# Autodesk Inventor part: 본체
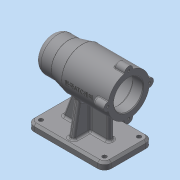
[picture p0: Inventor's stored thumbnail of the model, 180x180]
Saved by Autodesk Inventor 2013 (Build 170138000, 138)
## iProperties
Created: 2019-07
Part Number: 본체
Material: 일반
Document SubType Name: Modeling
Designer: dgall
Density: 1 g/cm^3
Author: dgall
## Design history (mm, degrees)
sketch "스케치1"
  geometry: L1 (0, 0)-(112, 0); L2 (112, 0)-(112, 70); L3 (112, 70)-(0, 70); L4 (0, 70)-(0, 0)
  constraints: 8 end point, 2 parallel, 1 horizontal, 1 perpendicular
  dimensions: "d5" = 70 distance of L1.end L2.end; "d6" = 112 distance of L2.end L3.end
extrude "돌출1" new body sketch "스케치1" distance "d7" = 10; taper "d8" = 0 deg
fillet "모깎기1" dims "d9" = 10
chamfer "모따기1" distance "d10" = 3; stored, may be unused: second distance "d11" = 2, angle "d12" = 45 deg
hole "구멍1" diameter "d15" = 6; stored, may be unused: countersink angle "d19" = 90 deg, drill point angle "d21" = 118 deg; dims "d13" = 10, "d14" = 10, "d16" = 6, "d17" = 4, "d18" = 2, "d20" = 27.5
hole "구멍2" diameter "d24" = 6; stored, may be unused: countersink angle "d28" = 90 deg, drill point angle "d30" = 118 deg; dims "d22" = 10, "d23" = 10, "d25" = 6, "d26" = 4, "d27" = 2, "d29" = 27.5
hole "구멍3" diameter "d33" = 6; stored, may be unused: countersink angle "d37" = 90 deg, drill point angle "d39" = 118 deg; dims "d31" = 10, "d32" = 10, "d34" = 6, "d35" = 4, "d36" = 2, "d38" = 27.5
hole "구멍4" diameter "d42" = 6; stored, may be unused: countersink angle "d46" = 90 deg, drill point angle "d48" = 118 deg; dims "d40" = 10, "d41" = 10, "d43" = 6, "d44" = 4, "d45" = 2, "d47" = 27.5
node "작업 평면2"
sketch "스케치2"
  geometry: L1 (0, 0)-(-112, 0); L2 (-56, 0)-(-56, 80); L3 (-56, 80)-(-112, 80); L4 (-56, 80)-(0, 80); L5 (-112, 80)-(-112, 101); L6 (-112, 101)-(-97, 101); L7 (-97, 101)-(-97, 101); L8 (-94, 104)-(-46, 104); L9 (-43, 101)-(-43, 101); L10 (-43, 101)-(-31.3, 101); L11 (-31, 100.7)-(-31, 97.5); L12 (-31, 97.5)-(-13.3, 97.5); L13 (-13, 97.2)-(-13, 96); L14 (-13, 96)-(-9.3, 96); L15 (-9, 95.7)-(-9, 90.5); L16 (-9, 90.5)-(-9, 90.5); L17 (-6, 87.5)-(-6, 80); L18 (0, 80)-(0, 95); L19 (-10, 105)-(-25, 105); L20 (-25, 105)-(-45, 110); L21 (-45, 110)-(-112, 110); L22 (-112, 110)-(-112, 101); A1 r 0.3 centre (-9.3, 95.7) between (-9, 95.7) and (-9.3, 96); A2 r 0.3 centre (-13.3, 97.2) between (-13, 97.2) and (-13.3, 97.5); A3 r 0.3 centre (-31.3, 100.7) between (-31, 100.7) and (-31.3, 101); A4 r 3 centre (-46, 101) between (-43, 101) and (-46, 104); A5 r 3 centre (-94, 101) between (-94, 104) and (-97, 101); A6 r 3 centre (-9, 87.5) between (-6, 87.5) and (-9, 90.5); A7 r 10 centre (-10, 95) between (0, 95) and (-10, 105); 7 further points
  constraints: 44 end point, 17 perpendicular, 15 point on line, 14 point on circle, 14 tangent, 7 centre point, 3 equal radius, 2 parallel, 1 collinear, 1 horizontal, 1 midpoint
  dimensions: "d50" = 112 distance of L1.start L1.end; "d54" = 80 distance of L2.start L2.end; "d55" = 21 distance of L3.end L5.end; "d57" = 48 diameter of point (-97, 104) L3; "d58" = 54 distance of point (-97, 104) point (-43, 104); "d59" = 56 distance from line of L2.end L5; "d60" = 42 diameter of L9.end L4; "d61" = 12 distance of L9.end point (-31, 101); "d62" = 35 diameter of L11.end L4; "d63" = 18 distance of L11.end point (-13, 97.5); "d64" = 32 diameter of L13.end L4; "d65" = 4 distance of L13.end point (-9, 96); "d66" = 21 diameter of L15.end L4; "d67" = 3 distance of L15.end point (-6, 90.5); "d68" = 0.3 radius of A1; "d69" = 3 radius of A4; "d70" = 50 diameter of point (0, 105) L4; "d71" = 25 distance of point (0, 105) L19.end; "d72" = 60 diameter of L20.end L4; "d73" = 45 horizontal distance of point (0, 105) L20.end; "d74" = 15 distance of L5.end L6.end; "d75" = 112 horizontal distance of point (0, 105) L21.end; "d76" = 3 radius of A6; "d77" = 10 radius of A7
revolve "회전1" sketch "스케치2" stored, may be unused: angle "d78" = 90 deg
sketch "스케치3"
  geometry: L1 (-30, 0)-(30, 0); L2 (0, -30)-(0, 30); A1 r 6 centre (-30, 0) between (-29.4, 5.97) and (-29.4, -5.97); A2 r 6 centre (0, 30) between (5.97, 29.4) and (-5.97, 29.4); A3 r 6 centre (0, -30) between (-5.97, -29.4) and (5.97, -29.4); A4 r 6 centre (30, 0) between (29.4, -5.97) and (29.4, 5.97); 2 further points
  constraints: 8 point on circle, 4 centre point, 4 coincident, 4 end point, 2 equal radius, 1 horizontal, 1 perpendicular, 13 other
  dimensions: "d79" = 60 distance of L1.start L1.end; "d80" = 60 distance of L2.start L2.end; "d81" = 12 diameter of A1; "d82" = 12 diameter of A3
extrude "돌출2" join sketch "스케치3" distance "d83" = 16; taper "d84" = 0 deg
hole "구멍5" sketch "스케치3" diameter "d85" = 3.242; stored, may be unused: countersink angle "d89" = 90 deg, drill point angle "d91" = 118 deg; dims "d86" = 8, "d87" = 4, "d88" = 2, "d90" = 11
fillet "모깎기2" dims "d92" = 3
fillet "모깎기3" dims "d93" = 1
node "작업 평면3"
sketch "스케치4"
  geometry: L1 (0, 0)-(0, 70); L2 (0, 35)-(20, 35); L3 (0, 0)-(112, 0); L4 (112, 0)-(112, 70); L5 (112, 35)-(87, 35); L6 (87, 39)-(87, 31); L7 (20, 39)-(20, 31); L8 (56, 0)-(56, 7); L9 (0, 70)-(112, 70); L10 (56, 70)-(56, 63); L11 (52, 7)-(60, 7); L12 (52, 63)-(60, 63); L13 (20, 39)-(52, 39); L14 (60, 39)-(87, 39); L15 (60, 63)-(60, 39); L16 (60, 31)-(60, 7); L17 (52, 63)-(52, 39); L18 (52, 31)-(52, 7); L19 (87, 31)-(60, 31); L20 (52, 31)-(20, 31); 4 further points
  constraints: 40 end point, 10 perpendicular, 9 parallel, 8 midpoint, 1 horizontal alignment, 1 vertical, 1 vertical alignment
  dimensions: "d95" = 70 distance of L1.start L1.end; "d100" = 112 distance of L1.start L3.end; "d101" = 70 distance of L3.end L4.end; "d102" = 25 distance of L5.start L5.end; "d103" = 8 distance of L7.start L7.end; "d104" = 67 distance of L7.start L6.start; "d105" = 92 horizontal distance of L5.start L7.start; "d106" = 4 distance of L5.end L6.start; "d107" = 4 distance of L2.end L7.end; "d109" = 8 distance of L11.end L11.start; "d114" = 7 distance from line of L9 L12.end; "d115" = 7 distance from line of L3 L11.end; "d116" = 24 distance of L12.end L14.start; "d117" = 32 distance of L18.start L7.end; "d118" = 27 distance of L6.end L16.start; "d119" = 24 distance of L18.start L11.start; "d120" = 24 distance of L16.start L11.end; "d121" = 8 distance of L12.start L12.end; "d122" = 63 distance from line of L3 L10.end; "d123" = 41.7732 distance of L5.end L8.end
extrude "돌출3" join sketch "스케치4" stored distance "d124" = 16; taper "d125" = 0 deg
feature "면 기울기1" dims angle "d126" = 20 deg
feature "면 기울기2" dims angle "d127" = 10 deg
fillet "모깎기4" dims "d128" = 3
fillet "모깎기5" dims "d129" = 1
fillet "모깎기6" dims "d130" = 3
node "작업 평면4"
sketch "스케치5"
  geometry: L1 (112, 110.171)-(112, 116) reference; L2 (112, 74.002)-(112, 85.998) reference; 3 further points
  constraints: 1 horizontal alignment, 1 midpoint, 1 other
  dimensions: "d132" = 42 distance from line of L1 point (70, 80)
feature "엠보싱1" sketch "스케치5" dims "d5" = 70, "d6" = 112, "d28" = 90 deg, "d133" = 0.5, "d134" = 0
chamfer "모따기2" distance "d137" = 1; stored, may be unused: second distance "d138" = 2, angle "d139" = 45 deg
node "솔리드1"
other parameters: "d49" = 35, "d131" = 5
